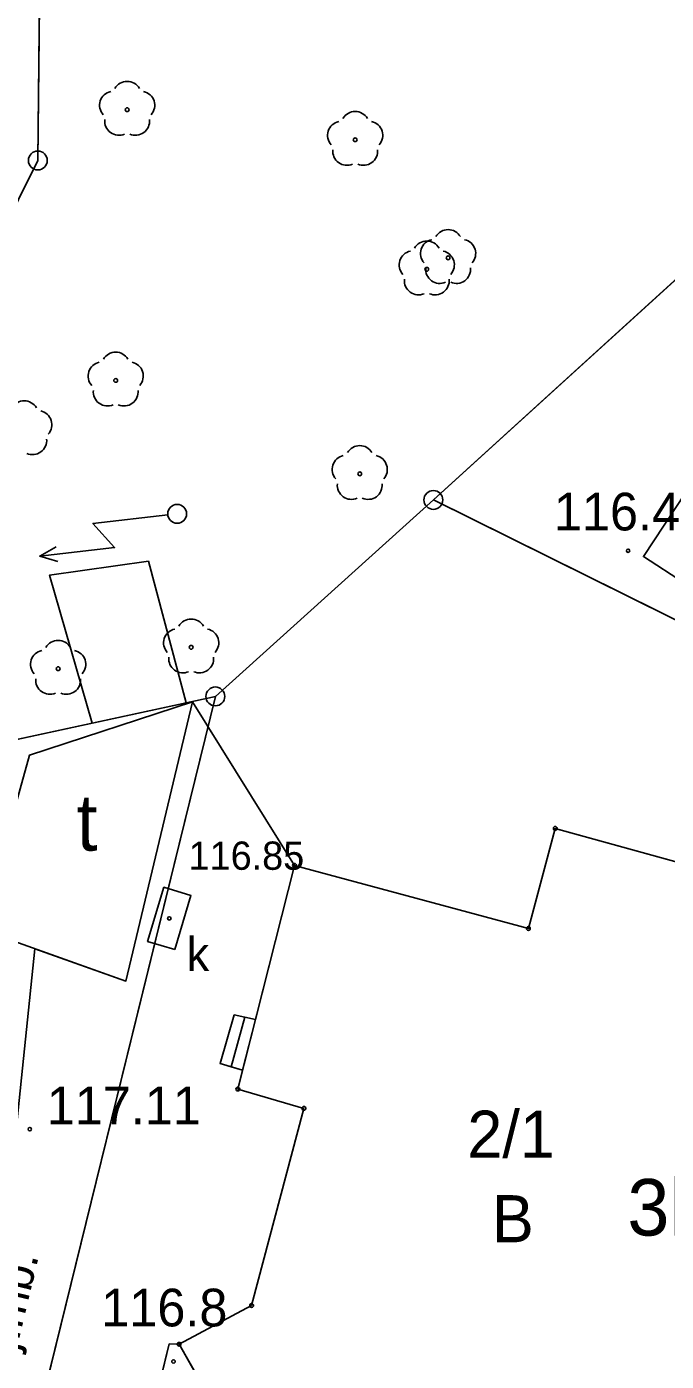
# Model space of a CAD drawing. Extents: x 6434771 to 6436222, y 5663454 to 5664782.
# Drawn here: x 6435581.61 to 6435598.58, y 5663735.7 to 5663771.1 of the extents above; entities that cross this region are included whole.
import ezdxf

# ---------------------------------------------------------------- set-up
doc = ezdxf.new("R2010")
doc.units = 0
for name, color, linetype in [('Warstwa 1', 7, 'Continuous'), ('Warstwa 10', 7, 'Continuous'), ('Warstwa 11', 7, 'Continuous'), ('Warstwa 12', 7, 'Continuous'), ('Warstwa 13', 7, 'Continuous'), ('Warstwa 15', 7, 'Continuous'), ('Warstwa 2', 7, 'Continuous'), ('Warstwa 25', 7, 'Continuous'), ('Warstwa 3', 7, 'Continuous'), ('Warstwa 36', 7, 'Continuous'), ('Warstwa 4', 7, 'Continuous'), ('Warstwa 40', 7, 'Continuous'), ('Warstwa 5', 7, 'Continuous'), ('Warstwa 6', 7, 'Continuous'), ('Warstwa 8', 7, 'Continuous')]:
    doc.layers.add(name, color=color, linetype=linetype)

msp = doc.modelspace()

# ---------------------------------------------------------------- linework, layer by layer
at = {"layer": 'Warstwa 1'}
for p, q in [((6435581.903, 5663767.556), (6435582.013, 5663777.505)), ((6435581.903, 5663767.556), (6435582.013, 5663777.505)), ((6435592.395, 5663758.549), (6435606.056, 5663770.975)), ((6435592.395, 5663758.549), (6435606.056, 5663770.975)), ((6435577.311, 5663758.31), (6435581.903, 5663767.556)), ((6435577.311, 5663758.31), (6435581.903, 5663767.556)), ((6435586.612, 5663753.338), (6435592.395, 5663758.549)), ((6435586.612, 5663753.338), (6435592.395, 5663758.549)), ((6435592.395, 5663758.549), (6435618.6, 5663745.562)), ((6435592.395, 5663758.549), (6435618.6, 5663745.562)), ((6435569.265, 5663749.587), (6435586.612, 5663753.338)), ((6435569.265, 5663749.587), (6435586.612, 5663753.338)), ((6435579.081, 5663722.727), (6435586.612, 5663753.338)), ((6435579.081, 5663722.727), (6435586.612, 5663753.338)), ((6435594.915, 5663747.18), (6435595.629, 5663749.838)), ((6435595.629, 5663749.838), (6435600.081, 5663748.602)), ((6435587.21, 5663742.922), (6435588.713, 5663748.855)), ((6435588.713, 5663748.855), (6435594.915, 5663747.18)), ((6435587.21, 5663742.922), (6435588.963, 5663742.409)), ((6435587.575, 5663737.181), (6435588.963, 5663742.409)), ((6435585.65, 5663736.152), (6435587.575, 5663737.181)), ((6435585.65, 5663736.152), (6435587.075, 5663733.653))]:
    msp.add_line(p, q, dxfattribs=at)
for points in [[(6435601.015, 5663759.31), (6435599.923, 5663760.013), (6435597.97, 5663757.047), (6435599.062, 5663756.343)], [(6435586.01, 5663753.195), (6435584.24, 5663745.786), (6435580.391, 5663747.154), (6435581.683, 5663751.78)], [(6435588.713, 5663748.855), (6435594.915, 5663747.18), (6435595.629, 5663749.838), (6435600.081, 5663748.602), (6435599.508, 5663746.512), (6435610.619, 5663743.552), (6435608.945, 5663736.929), (6435609.351, 5663736.823), (6435607.93, 5663731.513), (6435608.65, 5663729.941), (6435606.261, 5663728.559), (6435605.299, 5663730.051), (6435600.705, 5663731.295), (6435600.818, 5663731.722), (6435592.822, 5663733.961), (6435592.676, 5663733.478), (6435588.768, 5663734.521), (6435587.075, 5663733.653), (6435585.65, 5663736.152), (6435587.575, 5663737.181), (6435588.963, 5663742.409), (6435587.21, 5663742.922)]]:
    msp.add_lwpolyline(points, close=True, dxfattribs=at)
msp.add_circle((6435585.6, 5663758.181), 0.25, dxfattribs=at)
at = {"layer": 'Warstwa 10'}
for centre in [(6435581.903, 5663767.556), (6435592.395, 5663758.549), (6435592.395, 5663758.549), (6435586.612, 5663753.338), (6435586.612, 5663753.338)]:
    msp.add_circle(centre, 0.25, dxfattribs=at)
at = {"layer": 'Warstwa 11'}
for centre in [(6435584.273, 5663768.903), (6435590.322, 5663768.105), (6435592.787, 5663764.972), (6435592.221, 5663764.668), (6435583.969, 5663761.721), (6435590.443, 5663759.242), (6435585.971, 5663754.64), (6435582.442, 5663754.073)]:
    msp.add_circle(centre, 0.05, dxfattribs=at)
for centre, start, end in [((6435583.916, 5663769.019), 102.1471, 221.8529), ((6435584.273, 5663769.278), 30.1471, 149.8529), ((6435584.63, 5663769.019), 318.1471, 77.8529), ((6435590.322, 5663768.48), 30.1471, 149.8529), ((6435584.053, 5663768.6), 174.1471, 293.8529), ((6435584.493, 5663768.6), 246.1471, 5.8529), ((6435589.965, 5663768.221), 102.1471, 221.8529), ((6435590.679, 5663768.221), 318.1471, 77.8529), ((6435590.102, 5663767.802), 174.1471, 293.8529), ((6435590.542, 5663767.802), 246.1471, 5.8529), ((6435592.43, 5663765.088), 102.1471, 221.8529), ((6435592.787, 5663765.347), 30.1471, 149.8529), ((6435593.144, 5663765.088), 318.1471, 77.8529), ((6435591.864, 5663764.784), 102.1471, 221.8529), ((6435592.221, 5663765.043), 30.1471, 149.8529), ((6435592.578, 5663764.784), 318.1471, 77.8529), ((6435592.001, 5663764.365), 174.1471, 293.8529), ((6435592.567, 5663764.669), 174.1471, 293.8529), ((6435592.441, 5663764.365), 246.1471, 5.8529), ((6435593.007, 5663764.669), 246.1471, 5.8529), ((6435583.969, 5663762.096), 30.1471, 149.8529), ((6435583.612, 5663761.837), 102.1471, 221.8529), ((6435584.326, 5663761.837), 318.1471, 77.8529), ((6435583.749, 5663761.418), 174.1471, 293.8529), ((6435584.189, 5663761.418), 246.1471, 5.8529), ((6435581.543, 5663760.804), 30.1471, 149.8529), ((6435581.9, 5663760.545), 318.1471, 77.8529), ((6435581.763, 5663760.126), 246.1471, 5.8529), ((6435590.443, 5663759.617), 30.1471, 149.8529), ((6435590.086, 5663759.358), 102.1471, 221.8529), ((6435590.8, 5663759.358), 318.1471, 77.8529), ((6435590.223, 5663758.939), 174.1471, 293.8529), ((6435590.663, 5663758.939), 246.1471, 5.8529), ((6435585.971, 5663755.015), 30.1471, 149.8529), ((6435585.614, 5663754.756), 102.1471, 221.8529), ((6435586.328, 5663754.756), 318.1471, 77.8529), ((6435582.085, 5663754.189), 102.1471, 221.8529), ((6435582.442, 5663754.448), 30.1471, 149.8529), ((6435582.799, 5663754.189), 318.1471, 77.8529), ((6435585.751, 5663754.337), 174.1471, 293.8529), ((6435586.191, 5663754.337), 246.1471, 5.8529), ((6435582.222, 5663753.77), 174.1471, 293.8529), ((6435582.662, 5663753.77), 246.1471, 5.8529)]:
    msp.add_arc(centre, 0.375, start, end, dxfattribs=at)
at = {"layer": 'Warstwa 12'}
for centre in [(6435595.629, 5663749.838), (6435588.713, 5663748.855), (6435594.915, 5663747.18), (6435587.21, 5663742.922), (6435588.963, 5663742.409), (6435587.575, 5663737.181), (6435585.65, 5663736.152)]:
    msp.add_circle(centre, 0.05, dxfattribs=at)
at = {"layer": 'Warstwa 13'}
for centre in [(6435597.56, 5663757.203), (6435585.502, 5663735.695)]:
    msp.add_circle(centre, 0.045, dxfattribs=at)
at = {"layer": 'Warstwa 2'}
msp.add_lwpolyline([(6435583.347, 5663752.632), (6435582.217, 5663756.556), (6435584.837, 5663756.922), (6435585.836, 5663753.17)], close=True, dxfattribs=at)
msp.add_lwpolyline([(6435581.931, 5663721.843), (6435585.384, 5663736.162)], dxfattribs=at)
at = {"layer": 'Warstwa 25'}
msp.add_circle((6435581.69, 5663741.857), 0.045, dxfattribs=at)
at = {"layer": 'Warstwa 36'}
msp.add_line((6435587.396, 5663744.832), (6435587.036, 5663743.51), dxfattribs=at)
msp.add_lwpolyline([(6435587.114, 5663744.894), (6435587.678, 5663744.77), (6435587.336, 5663743.419), (6435586.737, 5663743.601)], close=True, dxfattribs=at)
at = {"layer": 'Warstwa 4'}
msp.add_lwpolyline([(6435585.535, 5663746.623), (6435584.816, 5663746.838), (6435585.247, 5663748.275), (6435585.966, 5663748.06)], close=True, dxfattribs=at)
at = {"layer": 'Warstwa 40'}
msp.add_line((6435585.352, 5663758.153), (6435583.364, 5663757.927), dxfattribs=at)
for points in [[(6435585.352, 5663758.153), (6435583.364, 5663757.927), (6435583.94, 5663757.288), (6435581.953, 5663757.062)], [(6435582.432, 5663756.919), (6435581.953, 5663757.062), (6435582.388, 5663757.308)]]:
    msp.add_lwpolyline(points, dxfattribs=at)
msp.add_circle((6435585.6, 5663758.181), 0.25, dxfattribs=at)
at = {"layer": 'Warstwa 6'}
for points in [[(6435548.671, 5663800.788), (6435521.147, 5663772.588), (6435523.103, 5663770.554), (6435543.163, 5663791.864), (6435547.892, 5663795.057), (6435552.721, 5663796.629), (6435556.818, 5663797.2), (6435563.282, 5663796.602), (6435571.928, 5663792.927), (6435578.259, 5663786.341), (6435582.013, 5663777.505), (6435581.903, 5663767.556), (6435577.311, 5663758.31), (6435571.527, 5663753.09), (6435533.459, 5663736.247), (6435548.335, 5663741.528), (6435569.265, 5663749.587), (6435586.612, 5663753.338), (6435592.395, 5663758.549), (6435606.056, 5663770.975), (6435613.539, 5663781.965), (6435615.412, 5663784.713), (6435621.643, 5663793.868), (6435632.116, 5663809.073)], [(6435533.459, 5663736.247), (6435571.527, 5663753.09), (6435577.311, 5663758.31), (6435581.903, 5663767.556), (6435582.013, 5663777.505), (6435578.259, 5663786.341), (6435571.928, 5663792.927), (6435563.282, 5663796.602), (6435556.818, 5663797.2), (6435552.721, 5663796.629), (6435547.892, 5663795.057)]]:
    msp.add_lwpolyline(points, dxfattribs=at)
for points in [[(6435626.306, 5663776.741), (6435628.564, 5663782.314), (6435631.491, 5663789.529), (6435621.643, 5663793.868), (6435615.412, 5663784.713), (6435620.876, 5663780.847), (6435618.974, 5663778.19), (6435613.539, 5663781.965), (6435606.056, 5663770.975), (6435592.395, 5663758.549), (6435618.6, 5663745.562), (6435624.75, 5663759.649), (6435630.409, 5663773.631)], [(6435585.89, 5663720.915), (6435606.104, 5663716.081), (6435618.6, 5663745.562), (6435592.395, 5663758.549), (6435586.612, 5663753.338), (6435579.081, 5663722.727)], [(6435581.354, 5663741.931), (6435578.096, 5663728.909), (6435564.805, 5663732.24), (6435563.667, 5663727.503), (6435570.839, 5663725.106), (6435579.081, 5663722.727), (6435586.612, 5663753.338), (6435569.265, 5663749.587), (6435548.335, 5663741.528), (6435548.772, 5663729.662), (6435551.767, 5663728.426), (6435553.74, 5663736.053), (6435553.014, 5663737.292), (6435551.682, 5663737.088), (6435550.472, 5663737.982), (6435550.23, 5663739.415), (6435550.983, 5663740.506), (6435558.522, 5663743.666), (6435569.854, 5663747.84), (6435570.984, 5663744.546)], [(6435599.508, 5663746.512), (6435600.081, 5663748.602), (6435595.629, 5663749.838), (6435594.915, 5663747.18), (6435588.713, 5663748.855), (6435587.21, 5663742.922), (6435588.963, 5663742.409), (6435587.575, 5663737.181), (6435585.65, 5663736.152), (6435587.075, 5663733.653), (6435588.768, 5663734.521), (6435592.676, 5663733.478), (6435592.822, 5663733.961), (6435600.818, 5663731.722), (6435600.705, 5663731.295), (6435605.362, 5663729.986), (6435606.261, 5663728.559), (6435608.65, 5663729.941), (6435607.93, 5663731.513), (6435609.351, 5663736.823), (6435608.945, 5663736.929), (6435610.619, 5663743.552)]]:
    msp.add_lwpolyline(points, close=True, dxfattribs=at)
msp.add_circle((6435585.391, 5663747.449), 0.045, dxfattribs=at)
at = {"layer": 'Warstwa 8'}
for p, q in [((6435584.24, 5663745.786), (6435586.01, 5663753.195)), ((6435586.01, 5663753.195), (6435588.713, 5663748.855)), ((6435587.678, 5663744.77), (6435588.713, 5663748.855)), ((6435581.333, 5663741.851), (6435581.827, 5663746.644)), ((6435581.827, 5663746.644), (6435584.24, 5663745.786)), ((6435586.737, 5663743.601), (6435587.114, 5663744.894)), ((6435587.114, 5663744.894), (6435587.396, 5663744.832)), ((6435587.396, 5663744.832), (6435587.678, 5663744.77)), ((6435586.737, 5663743.601), (6435587.036, 5663743.51)), ((6435587.036, 5663743.51), (6435587.336, 5663743.419)), ((6435587.21, 5663742.922), (6435587.336, 5663743.419)), ((6435587.21, 5663742.922), (6435588.963, 5663742.409)), ((6435587.575, 5663737.181), (6435588.963, 5663742.409)), ((6435585.65, 5663736.152), (6435587.575, 5663737.181)), ((6435583.658, 5663729.002), (6435585.384, 5663736.162)), ((6435585.384, 5663736.162), (6435585.65, 5663736.152))]:
    msp.add_line(p, q, dxfattribs=at)

# ---------------------------------------------------------------- texts
at = {"layer": 'Warstwa 13'}
for s, p in [('116.4', (6435595.594, 5663757.741)), ('116.8', (6435583.586, 5663736.625))]:
    msp.add_text(s, height=1, dxfattribs=at).set_placement(p)
at = {"layer": 'Warstwa 15'}
msp.add_text('2/1', height=1.25, dxfattribs=at).set_placement((6435593.296, 5663741.099))
at = {"layer": 'Warstwa 2'}
msp.add_text('B', height=1.25, dxfattribs=at).set_placement((6435593.947, 5663738.857))
at = {"layer": 'Warstwa 25'}
msp.add_text('117.11', height=1, dxfattribs=at).set_placement((6435582.139, 5663741.986))
at = {"layer": 'Warstwa 3'}
for s, p in [('t', (6435582.927, 5663749.246)), ('3k', (6435597.542, 5663739.035))]:
    msp.add_text(s, height=1.5, dxfattribs=at).set_placement(p)
at = {"layer": 'Warstwa 5'}
msp.add_text('k', height=0.9, dxfattribs=at).set_placement((6435585.847, 5663746.055))
at = {"layer": 'Warstwa 6'}
msp.add_text('116.85', height=0.75, dxfattribs=at).set_placement((6435585.902, 5663748.738))
at = {"layer": 'Warstwa 8'}
msp.add_text('j.mb.', height=0.9, rotation=76.6446, dxfattribs=at).set_placement((6435581.33, 5663735.957))

doc.saveas('drawing.dxf')
